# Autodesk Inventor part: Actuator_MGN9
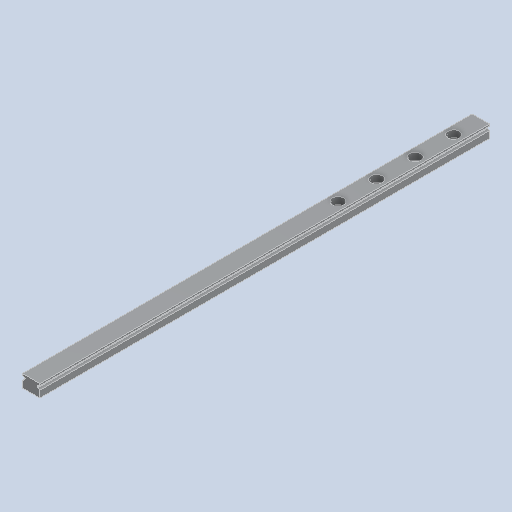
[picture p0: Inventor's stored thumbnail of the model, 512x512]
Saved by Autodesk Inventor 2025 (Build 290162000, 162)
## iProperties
Created: 2016-10
Part Number: Actuator_MGN9
Material: Библиотека материалов (ГОСТ)|Сталь 40 ГОСТ 535-88
Document SubType Name: Modeling
Designer: Ryzen5700u
Density: 7.83 g/cm^3
Appearance: Default
Author: Ryzen5700u
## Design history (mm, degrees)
feature "Solido1"
node "Solido2"
